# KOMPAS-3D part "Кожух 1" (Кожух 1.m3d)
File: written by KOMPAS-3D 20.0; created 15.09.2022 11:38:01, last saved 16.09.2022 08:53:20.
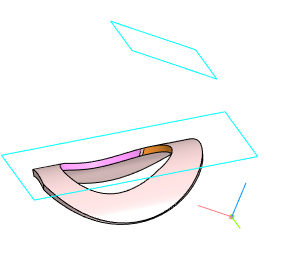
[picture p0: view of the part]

Document properties: Полное имя файла: D:\YAKOVLEV\ПРОЕКТЫ\ДЦ-2. ДП-7 Газопровод Окожушивание\ПРОБА Соединение труб. Окожушивание\ПРОБА 2\Кожух 1.m3d

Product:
- Part/product: Кожух 1
    Материал: Сталь 45  ГОСТ 1050-2013 (density 7810 kg/m3)
    Масса: 1603.28

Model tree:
1. Эскиз:1  (with: Обечайка:1)  (labels: Кожух 1 (трубы))
2. Обечайка:1  (labels: Кожух 1 (трубы))
     Расстояние 1 = -2450; Смещение 1 = -50; Толщина листового тела = 90
3. Сгиб(1) - Обечайка:1
     Радиус сгиба = 910; Коэффициент = 0.4; Величина сгиба = 10; Зазор = 1
4. Касательная плоскость:1  (with: Обечайка:1)
5. Смещенная плоскость:1  (with: Обечайка:1)  (labels: Кожух 1 (трубы))
6. Эскиз:2  (with: Обечайка:1)  (labels: Кожух 1 (трубы))
7. Вырез в листовом теле:2
     Глубина выреза = 2400
8. Разогнуть:1  (with: Обечайка:1)
9. Эскиз:3  (with: Обечайка:1, Вырез в листовом теле:2)
10. Вырез в листовом теле:3
     Глубина выреза = 1000
11. Эскиз:4  (with: Обечайка:1, Вырез в листовом теле:2, Вырез в листовом теле:3)
12. Вырез в листовом теле:4
     Глубина выреза = 1000
13. Эскиз:5  (with: Обечайка:1, Вырез в листовом теле:3, Вырез в листовом теле:4)
14. Вырез в листовом теле:5
     Глубина выреза = 10
15. Фаска:1  (with: Вырез в листовом теле:2, Вырез в листовом теле:3, Вырез в листовом теле:4)
     Угол = 45; Длина 1 = 3; Длина 2 = 3
16. Согнуть:1  (with: Обечайка:1)
17. Развертка  (labels: Сталь 45  ГОСТ 1050-2013)

Expressions: v207*2
Referenced files in D:\YAKOVLEV\ПРОЕКТЫ\ДЦ-2. ДП-7 Газопровод Окожушивание\ПРОБА Соединение труб. Окожушивание\ПРОБА 2\: Соединение труб. Окожушивание -2.a3d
